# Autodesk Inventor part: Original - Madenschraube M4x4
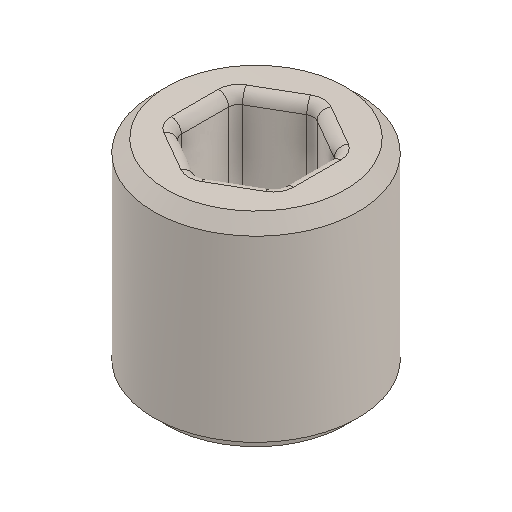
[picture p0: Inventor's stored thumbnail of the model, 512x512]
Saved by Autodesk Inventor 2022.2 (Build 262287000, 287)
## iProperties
Created: 2024-09
Part Number: Original - Madenschraube M4x4
Material: Generico
Document SubType Name: Modeling
Designer: 18907419
Density: 1 g/cm^3
Appearance: Default
Author: 18907419
Revision Number: ANY
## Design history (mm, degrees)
feature "Fase1"
node "Solido1"
